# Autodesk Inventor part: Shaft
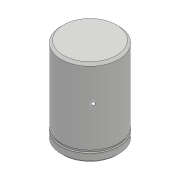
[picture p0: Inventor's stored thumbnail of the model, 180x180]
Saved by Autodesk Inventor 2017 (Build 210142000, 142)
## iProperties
Created: 2016-08
Part Number: Shaft
Material: Generic
Document SubType Name: Modeling
Designer: Sandeep
Density: 1 g/cm^3
Appearance: Default
Author: Sandeep
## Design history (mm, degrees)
sketch "Sketch1"
  geometry: C1 r 25 at (0, 0); 1 further point
  constraints: 1 centre point, 1 coincident
  dimensions: "d0" = 50 diameter of C1
extrude "Extrusion1" new body sketch "Sketch1" stored distance "d1" = 75; taper "d2" = 0 deg
sketch "Sketch2"
  geometry: L1 (-25, -37.5)-(-25, 37.5) reference; L2 (-25, -30)-(-23.5, -30); L3 (-23.5, -30)-(-23.5, -27.5); L4 (-23.5, -27.5)-(-25, -27.5); L5 (-25, -27.5)-(-25, -30); L6 (0, 0)-(0, -83)
  constraints: 10 end point, 2 parallel, 1 horizontal, 1 perpendicular, 1 point on line, 1 vertical
  dimensions: "d3" = 2.5 distance between parallel lines of L2 L4; "d4" = 47 diameter of L3 L6; "d5" = 7.5 distance from line of L2 L1.start
revolve "Revolution1" sketch "Sketch2" stored, may be unused: angle "d6" = 90 deg
chamfer "Chamfer1" distance "d7" = 2; stored, may be unused: second distance "d8" = 2, angle "d9" = 45 deg
body "Solid1"
other parameters: "d10" = 0
